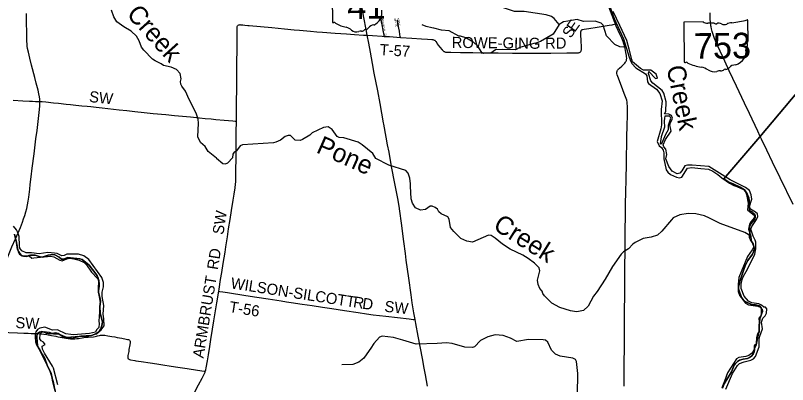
# Model space of a CAD drawing. Extents: x -51392 to 1635000, y 156707 to 696232.
# Drawn here: x 128704 to 149662, y 467379 to 477391 of the extents above; entities that cross this region are included whole.
import ezdxf

# ---------------------------------------------------------------- set-up
doc = ezdxf.new("R2010")
doc.units = 0
for name, color, linetype in [('GM_X_County_Road', 7, 'Continuous'), ('GM_X_Major_River', 7, 'Continuous'), ('GM_X_Major_River_Text', 7, 'Continuous'), ('GM_X_Minor_River', 7, 'Continuous'), ('GM_X_Minor_River_Text', 7, 'Continuous'), ('GM_X_State_Route', 7, 'Continuous'), ('GM_X_State_Shield', 7, 'Continuous'), ('GM_X_Township', 7, 'Continuous'), ('GM_X_Township_Road', 7, 'Continuous'), ('GM_X_Township_Road_Text', 7, 'Continuous'), ('GM_X_Township_Subdivision', 7, 'Continuous'), ('GM_X_Township_Subdivision_Text', 7, 'Continuous'), ('GM_X_US_Route', 7, 'Continuous')]:
    doc.layers.add(name, color=color, linetype=linetype)

msp = doc.modelspace()

# ---------------------------------------------------------------- linework, layer by layer
at = {"layer": 'GM_X_County_Road'}
for points in [[(144988, 477162), (144974, 477196), (144858, 477503), (144814, 477627), (144799, 477673), (144787, 477721), (144778, 477769), (144766, 477850), (144758, 477916)], [(145227, 467332), (145227, 467463), (145229, 467742), (145231, 468054), (145232, 468284), (145234, 468480), (145234, 468645), (145236, 468809), (145236, 468940), (145239, 469202), (145240, 469448), (145242, 469727), (145243, 470055), (145249, 470514), (145249, 470662), (145252, 470908), (145255, 471154), (145257, 471384), (145258, 471564), (145262, 471958), (145264, 472122), (145266, 472302), (145270, 472581), (145280, 472958), (145288, 473352), (145292, 473581), (145297, 473893), (145301, 474123), (145307, 474369), (145314, 474713), (145314, 474943), (145312, 474992), (145306, 475042), (145295, 475090), (145280, 475137), (145230, 475276), (145154, 475476), (145053, 475736), (145037, 475782), (145030, 475813), (145028, 475829), (145028, 475845), (145029, 475860), (145033, 475875), (145039, 475890), (145046, 475904), (145055, 475917), (145065, 475929), (145076, 475941), (145100, 475964), (145160, 476019), (145209, 476064), (145243, 476100), (145263, 476126), (145272, 476140), (145280, 476155), (145286, 476171), (145290, 476187), (145293, 476203), (145295, 476220), (145296, 476236), (145294, 476270), (145290, 476303), (145276, 476384), (145253, 476496), (145234, 476576), (145220, 476624), (145198, 476686), (145161, 476777), (145121, 476867), (145065, 476986), (145011, 477105), (144988, 477162)]]:
    msp.add_lwpolyline(points, dxfattribs=at)
at = {"layer": 'GM_X_Major_River'}
for points in [[(144803, 477732), (144953, 477307), (145102, 476988), (145207, 476761), (145359, 476262), (145411, 476143), (145437, 476087), (145546, 475971), (145810, 475810), (145841, 475757), (145863, 475591), (145883, 475541), (146106, 475394), (146198, 475271), (146257, 475073), (146234, 474841), (146238, 474424), (146224, 474314), (146127, 473973), (146174, 473857), (146236, 473805), (146288, 473733), (146305, 473662), (146299, 473503)], [(146357, 473505), (146381, 473616), (146354, 473760), (146300, 473825), (146288, 473883), (146347, 474027), (146506, 474251), (146470, 474427), (146481, 474489), (146519, 474549), (146535, 474603), (146508, 474677), (146440, 474712), (146318, 474722), (146354, 474784), (146369, 475049), (146304, 475281), (146256, 475351), (146003, 475553), (145953, 475619), (145886, 475819), (145898, 475871), (146073, 475685), (146131, 475686), (146092, 475801), (145948, 475911), (145752, 475906), (145670, 475950), (145457, 476137), (145431, 476199), (145364, 476474), (145299, 476709), (145109, 477118), (144924, 477495)], [(146322, 474605), (146311, 474526), (146318, 474358), (146231, 474097), (146200, 473913), (146252, 473917), (146359, 474173), (146432, 474299), (146426, 474413), (146495, 474607), (146463, 474658), (146329, 474656)], [(146329, 474656), (146322, 474605)], [(146299, 473503), (146369, 473200), (146414, 473144), (146482, 473081), (146647, 473001), (146727, 472989), (146791, 473004), (146944, 473250), (147062, 473269), (147310, 473238), (147520, 473219), (147636, 473167), (147773, 473080), (147881, 472983), (148086, 472841), (148205, 472782), (148285, 472751), (148463, 472667), (148520, 472603), (148550, 472536), (148592, 472295), (148574, 472119), (148767, 471965), (148754, 471897), (148663, 471794), (148631, 471732), (148601, 471596), (148662, 471407), (148677, 471292), (148732, 471160), (148735, 471103), (148703, 471034), (148573, 470850), (148338, 470287), (148320, 470091), (148333, 469974), (148421, 469709), (148522, 469588), (148599, 469545), (148853, 469509), (148915, 469478), (148973, 469426), (148982, 469357), (148935, 469242), (148906, 469164), (148873, 468761), (148814, 468459), (148732, 468275)], [(147988, 467253), (148166, 467680), (148301, 467896), (148361, 467951), (148484, 467999), (148668, 468037), (148741, 468075), (148789, 468144), (148888, 468398), (148892, 468610), (148906, 468687), (148980, 468886), (148958, 469067), (148989, 469181), (149051, 469247), (149092, 469316), (149103, 469429), (149067, 469481), (149015, 469475), (148950, 469534), (148878, 469567), (148692, 469598), (148606, 469637), (148481, 469779), (148407, 469980), (148404, 470106), (148431, 470232), (148460, 470302), (148586, 470525), (148770, 470919), (148801, 471057), (148805, 471237), (148779, 471298), (148728, 471406), (148669, 471593), (148688, 471665), (148822, 471858), (148853, 471938), (148845, 472007), (148794, 472057), (148654, 472139), (148633, 472207), (148689, 472405), (148674, 472529), (148625, 472640), (148523, 472727), (148105, 472933), (147525, 473293), (147075, 473333), (146944, 473330), (146874, 473308), (146793, 473175), (146734, 473115), (146664, 473094), (146528, 473165), (146437, 473296), (146357, 473505)], [(148732, 468275), (148684, 468217), (148615, 468170), (148529, 468138), (148335, 468116), (148276, 468074), (148028, 467698), (147952, 467472), (147879, 467288)]]:
    msp.add_lwpolyline(points, dxfattribs=at)
at = {"layer": 'GM_X_Minor_River'}
for points in [[(143460, 477143), (143330, 477310), (143256, 477360), (143113, 477411), (142509, 477497), (142254, 477494), (141899, 477619), (141475, 477674), (140841, 477787), (140457, 477962), (140338, 478077)], [(134164, 473520), (133933, 473701), (133855, 473836), (133726, 473948), (133654, 474095), (133676, 474467), (133668, 474575), (133607, 474740), (133422, 475109), (133319, 475338), (133221, 475472), (133192, 475527), (133188, 475597), (133206, 475675), (133177, 475817), (133077, 475928), (132935, 475988), (132721, 476037), (132661, 476083), (132498, 476164), (132428, 476204), (132185, 476447), (132127, 476532), (132062, 476700), (131990, 476825), (131843, 476961), (131645, 477086), (131457, 477215), (131376, 477351), (131313, 477538)], [(145272, 476551), (145218, 476535), (145112, 476541), (144970, 476606), (144751, 476839), (144654, 477132), (144604, 477186), (144441, 477236), (144122, 477223), (143947, 477278), (143702, 477239), (143576, 477221), (143460, 477143), (143297, 476885), (142960, 476682), (142827, 476638), (142773, 476629), (142391, 476526), (142280, 476458), (141926, 476469), (141732, 476460), (141608, 476372), (141419, 476356), (141360, 476385), (141252, 476555), (141137, 476670), (141085, 476698), (140929, 476787), (140787, 476833), (140737, 476829), (140475, 476974), (140265, 476989), (140061, 477042), (140005, 477052), (139851, 477087), (139742, 477135)], [(138486, 473513), (138403, 473647), (138118, 473880), (138002, 473957), (137620, 474072), (137492, 474083), (137440, 474107), (137297, 474300), (137189, 474368), (137063, 474352), (136756, 474203), (136698, 474147), (136497, 474024), (136431, 473998), (136299, 474012), (136172, 474133), (136104, 474139), (136023, 474105), (135899, 474005), (135775, 473950), (135709, 473940), (134870, 473884), (134800, 473851), (134701, 473721), (134639, 473687), (134603, 473631), (134592, 473531)], [(134164, 473520), (134329, 473378), (134401, 473368), (134467, 473391), (134592, 473531)], [(148662, 471407), (148500, 471502), (147836, 471751), (147547, 471891), (147409, 471953), (147173, 472013), (146967, 472019), (146740, 471980), (146561, 471900), (146511, 471846), (146246, 471538), (146129, 471430), (145960, 471380), (145739, 471345), (145526, 471233), (145464, 471185), (145340, 471064), (145213, 470983), (145147, 470919), (144912, 470581), (144714, 470238), (144497, 469901), (144398, 469779), (144251, 469504), (144124, 469391), (143988, 469358), (143929, 469350), (143767, 469376), (143478, 469472), (143259, 469586), (143068, 469786), (143019, 469851), (142999, 469911), (142942, 469982), (142893, 470095), (142873, 470207), (142938, 470467), (142916, 470543), (142797, 470671), (142618, 470801), (142473, 470890), (142134, 471049), (141927, 471185), (141724, 471353), (141614, 471424), (141548, 471429), (141108, 471242), (140954, 471268), (140796, 471339), (140606, 471533), (140511, 471640), (140479, 471863), (140441, 471926), (140256, 472007), (140194, 472062), (140161, 472132), (140095, 472185), (140019, 472220), (139965, 472222), (139832, 472131), (139698, 472112), (139564, 472173), (139483, 472296), (139444, 472413), (139429, 472764), (139424, 472826), (139409, 472977), (139366, 473115), (139297, 473182), (138843, 473334), (138486, 473513)], [(129850, 467367), (129734, 467821), (129709, 467875), (129489, 468226), (129434, 468338), (129425, 468416), (129506, 468464), (129464, 468526), (129398, 468567), (129367, 468623), (129374, 468746), (129420, 468803), (129485, 468817), (129617, 468800), (129740, 468751), (129875, 468753), (130088, 468667), (130329, 468681), (130383, 468687), (130625, 468683), (130908, 468759), (131033, 468866), (131110, 468974), (131100, 469160), (131089, 469284), (131107, 469525), (131061, 469768), (131054, 469888), (131093, 470030), (131090, 470144), (131046, 470285), (130695, 470775), (130556, 470867), (130418, 470914), (130348, 470912), (130098, 470914), (130027, 470877), (129961, 470868), (129834, 470931), (129766, 470947), (129586, 470959), (129351, 470923), (129143, 470951), (128995, 470952), (128877, 471007), (128826, 471080), (128810, 471150), (128802, 471397), (128787, 471447), (128755, 471521), (128736, 471572), (128653, 471672)], [(128690, 471432), (128754, 471132), (128775, 470980), (128814, 470917), (128882, 470873), (129080, 470867), (129152, 470810), (129206, 470812), (129663, 470862), (129745, 470845), (129908, 470750), (129974, 470737), (130099, 470792), (130181, 470806), (130235, 470797), (130291, 470785), (130431, 470751), (130566, 470688), (130630, 470625), (130768, 470430), (130935, 470258), (130965, 470200), (130947, 470041), (130952, 469913), (131004, 469608), (130969, 469099), (130975, 469035), (130963, 468923), (130900, 468867), (130876, 468797), (130710, 468764), (130277, 468724), (130207, 468733), (130067, 468750), (129845, 468862), (129709, 468855), (129498, 468933), (129369, 468912), (129301, 468869), (129254, 468811), (129242, 468739), (129237, 468661), (129248, 468534), (129271, 468456), (129370, 468303), (129425, 468168), (129541, 467962), (129626, 467765), (129727, 467458), (129781, 467185)], [(143958, 467107), (143967, 467678), (143932, 468005), (143904, 468055), (143832, 468094), (143492, 468149), (143361, 468200), (143255, 468315), (143159, 468527), (143089, 468579), (143032, 468596), (142627, 468597), (142316, 468546), (142137, 468636), (141941, 468709), (141727, 468723), (141522, 468673), (141329, 468576), (141163, 468403), (141109, 468382), (140905, 468392), (140555, 468491), (140407, 468506), (140153, 468494), (139584, 468477), (139216, 468584), (138970, 468656), (138658, 468693), (138590, 468664), (138428, 468491), (138349, 468367), (138306, 468303), (138164, 468096), (138025, 467985), (137860, 467924), (137566, 467913)]]:
    msp.add_lwpolyline(points, dxfattribs=at)
at = {"layer": 'GM_X_State_Route'}
for points in [[(138698, 474475), (138600, 475007), (138536, 475346), (138445, 475829), (138397, 476087), (138339, 476394), (138294, 476636), (138255, 476852), (138224, 477011), (138164, 477333), (138051, 477929), (138042, 477970), (138026, 478048), (138001, 478179), (137981, 478287)], [(147581, 477111), (147576, 477139), (147570, 477187), (147557, 477313), (147557, 477458)], [(149812, 472261), (149463, 472985), (149253, 473412), (149097, 473737), (148956, 474033), (148921, 474108), (148851, 474256), (148628, 474731), (148497, 475014), (148278, 475473), (148081, 475888), (147956, 476155), (147830, 476422), (147734, 476631), (147704, 476706), (147679, 476767), (147616, 476959), (147598, 477029), (147585, 477085), (147581, 477111)], [(139892, 467339), (139835, 467645), (139801, 467823), (139754, 468081), (139638, 468694), (139574, 469032), (139554, 469140), (139519, 469323), (139491, 469484), (139473, 469598), (139442, 469809), (139378, 470264), (139311, 470752), (139289, 470931), (139248, 471257), (139180, 471761), (139136, 472086), (139116, 472216), (139080, 472426), (139004, 472829), (138915, 473296), (138844, 473684), (138807, 473877), (138770, 474087), (138704, 474442), (138698, 474475)]]:
    msp.add_lwpolyline(points, dxfattribs=at)
at = {"layer": 'GM_X_State_Shield'}
for p, q in [((137297, 478273), (137307, 477217)), ((148589, 476700), (148584, 477253)), ((146844, 477192), (146854, 476136)), ((147371, 477216), (146861, 477211)), ((148589, 476701), (148589, 476700))]:
    msp.add_line(p, q, dxfattribs=at)
for centre, radius, start, end in [((138284, 477472), 369, 292.8474, 9.5244), ((137323, 477214), 16.3, 172.4969, 258.8452), ((137325, 477323), 124, 267.8775, 281.1424), ((137352, 477156), 44.8, 30.2869, 93.8103), ((137908, 478111), 1066, 240.9515, 257.737), ((137603, 476745), 334, 47.7227, 76.3745), ((138202, 476977), 31.8, 66.2903, 133.187), ((138187, 477122), 119, 283.4117, 323.8157), ((138445, 476931), 202, 94.9417, 143.1153), ((137960, 477157), 212, 231.2389, 286.8304), ((138086, 476792), 174, 86.2337, 111.7485), ((138099, 477079), 113, 269.3156, 316.0878)]:
    msp.add_arc(centre, radius, start, end, dxfattribs=at)
for centre, major_axis, start_param, end_param in [((147951, 478662), (1845, 17), 4.814394, 5.042369), ((148565, 477255), (19.4, 0.2), 6.141152, 7.989035), ((146864, 477195), (20.2, 0.2), 1.712693, 3.28349), ((147491, 477339), (196, 2), 4.042523, 4.731795), ((147563, 476624), (702, 7), 1.404758, 1.657858), ((147716, 477208), (56.4, 0.5), 3.836095, 5.185415), ((147800, 477087), (117, 1), 0.950623, 2.079405), ((147950, 477256), (141, 1), 4.081561, 5.145723), ((148203, 476901), (371, 3), 1.699011, 2.107814), ((148585, 476660), (30, 0.3), 1.883978, 3.671073), ((148395, 476588), (180, 2), 5.934695, 6.695948), ((148568, 476698), (20.7, 0.2), 5.05454, 6.418171), ((148075, 476394), (462, 4), 5.101752, 6.440018), ((148661, 476470), (131, 1), 2.387724, 3.262537), ((146874, 476134), (20.3, 0.2), 3.00124, 4.508301), ((146876, 476242), (155, 1), 4.665946, 4.897461), ((146910, 476075), (56, 0.5), 0.519207, 1.627899), ((147607, 477031), (1333, 13), 4.195997, 4.488961), ((147223, 475665), (417, 4), 0.823519, 1.323587), ((147953, 476044), (149, 1), 4.937069, 5.64225), ((148275, 475853), (253, 2), 1.647645, 2.488434), ((147670, 476077), (265, 2), 4.026481, 4.996735), ((147826, 475713), (217, 2), 1.495662, 1.94098), ((147843, 476000), (141, 1), 4.691044, 5.507374), ((147971, 475899), (39.7, 0.4), 1.147584, 2.315152)]:
    msp.add_ellipse(centre, major_axis=major_axis, ratio=0.8, start_param=start_param, end_param=end_param, dxfattribs=at)
at = {"layer": 'GM_X_Township'}
for points in [[(152114, 477913), (148909, 474096), (147936, 472955), (148047, 472875), (148207, 472813), (148377, 472734), (148489, 472659), (148569, 472551), (148611, 472445), (148628, 472288), (148622, 472180), (148628, 472128), (148648, 472078), (148704, 472062), (148756, 472013), (148782, 471963), (148787, 471911), (148765, 471853), (148671, 471747), (148634, 471683), (148630, 471633), (148638, 471527), (148626, 471423), (148629, 471363), (148653, 471307), (148727, 471196), (148755, 471090), (148755, 471038), (148741, 470980), (148706, 470920), (148583, 470746), (148515, 470600), (148464, 470470), (148367, 470176), (148329, 470017), (148327, 469955), (148334, 469895), (148368, 469791), (148456, 469683), (148508, 469634), (148680, 469546), (148796, 469539), (148900, 469511), (148946, 469461), (148958, 469406), (148952, 469290), (148932, 469238), (148895, 469182), (148899, 469082), (148887, 468974), (148888, 468810), (148858, 468758), (148826, 468652), (148817, 468487), (148765, 468437), (148768, 468321), (148756, 468269), (148726, 468205), (148682, 468147), (148630, 468113), (148573, 468089), (148461, 468068), (148353, 468042), (148299, 468008), (148248, 467954), (148216, 467902), (148141, 467726), (148037, 467564), (147944, 467398), (147898, 467284)], [(147898, 467284), (147944, 467398), (148037, 467564), (148141, 467726), (148216, 467902), (148248, 467954), (148299, 468008), (148353, 468042), (148461, 468068), (148573, 468089), (148630, 468113), (148682, 468147), (148726, 468205), (148756, 468269), (148768, 468321), (148765, 468437), (148817, 468487), (148826, 468652), (148858, 468758), (148888, 468810), (148887, 468974), (148899, 469082), (148895, 469182), (148932, 469238), (148952, 469290), (148958, 469406), (148946, 469461), (148900, 469511), (148796, 469539), (148680, 469546), (148508, 469634), (148456, 469683), (148368, 469791), (148334, 469895), (148327, 469955), (148329, 470017), (148367, 470176), (148464, 470470), (148515, 470600), (148583, 470746), (148706, 470920), (148741, 470980), (148755, 471038), (148755, 471090), (148727, 471196), (148653, 471307), (148629, 471363), (148626, 471423), (148638, 471527), (148630, 471633), (148634, 471683), (148671, 471747), (148765, 471853), (148787, 471911), (148782, 471963), (148756, 472013), (148704, 472062), (148648, 472078), (148628, 472128), (148622, 472180), (148628, 472288), (148611, 472445), (148569, 472551), (148489, 472659), (148377, 472734), (148207, 472813), (148047, 472875), (147936, 472955), (148909, 474096), (152114, 477913)], [(128677, 471456), (128728, 471229), (128760, 471041), (128796, 470983), (128822, 470930), (128868, 470880), (128924, 470858), (129014, 470852), (129064, 470876), (129116, 470887), (129240, 470889), (129379, 470847), (129431, 470838), (129593, 470886), (129715, 470904), (129777, 470901), (129887, 470837), (129955, 470779), (130014, 470780), (130118, 470822), (130448, 470793), (130512, 470769), (130704, 470618), (130890, 470385), (130926, 470325), (130950, 470263), (130975, 470128), (130975, 470048), (130955, 469924), (130955, 469874), (131000, 469704), (131008, 469639), (130995, 469485), (131001, 469315), (131064, 469076), (131062, 469016), (131020, 468892), (130987, 468840), (130941, 468788), (130887, 468754), (130767, 468707), (130482, 468694), (130310, 468652), (130255, 468628), (130197, 468644), (130075, 468647), (130023, 468655), (129863, 468762), (129801, 468786), (129647, 468758), (129538, 468773), (129486, 468797), (129416, 468815), (129358, 468803), (129306, 468767), (129293, 468727), (129288, 468711), (129282, 468655), (129305, 468441), (129331, 468379), (129367, 468324), (129426, 468202), (129500, 468084), (129562, 467907), (129677, 467674), (129705, 467554), (129715, 467448), (129782, 467211)], [(129782, 467211), (129715, 467448), (129705, 467554), (129677, 467674), (129562, 467907), (129500, 468084), (129426, 468202), (129367, 468324), (129331, 468379), (129305, 468441), (129282, 468655), (129288, 468711), (129293, 468727), (129306, 468767), (129358, 468803), (129416, 468815), (129486, 468797), (129538, 468773), (129647, 468758), (129801, 468786), (129863, 468762), (130023, 468655), (130075, 468647), (130197, 468644), (130255, 468628), (130310, 468652), (130482, 468694), (130767, 468707), (130887, 468754), (130941, 468788), (130987, 468840), (131020, 468892), (131062, 469016), (131064, 469076), (131001, 469315), (130995, 469485), (131008, 469639), (131000, 469704), (130955, 469874), (130955, 469924), (130975, 470048), (130975, 470128), (130950, 470263), (130926, 470325), (130890, 470385), (130704, 470618), (130512, 470769), (130448, 470793), (130118, 470822), (130014, 470780), (129955, 470779), (129887, 470837), (129777, 470901), (129715, 470904), (129593, 470886), (129431, 470838), (129379, 470847), (129240, 470889), (129116, 470887), (129064, 470876), (129014, 470852), (128924, 470858), (128868, 470880), (128822, 470930), (128796, 470983), (128760, 471041), (128728, 471229), (128677, 471456)]]:
    msp.add_lwpolyline(points, dxfattribs=at)
at = {"layer": 'GM_X_Township_Road'}
for points in [[(134702, 474522), (134702, 474568), (134703, 474618), (134704, 474831), (134705, 474929), (134708, 475126), (134709, 475323), (134711, 475651), (134714, 475930), (134716, 476176), (134718, 476405), (134721, 476898), (134721, 476947), (134719, 477062), (134719, 477078), (134722, 477094), (134728, 477109), (134738, 477122), (134751, 477132), (134766, 477137), (134781, 477141), (134796, 477142), (134815, 477141), (134845, 477139), (134877, 477136), (134927, 477130), (135010, 477122), (135044, 477119), (135664, 477062), (136007, 477029), (136269, 477005), (136416, 476992), (136710, 476964), (136889, 476948), (137036, 476937), (137380, 476912), (137691, 476889), (137903, 476874), (138149, 476857), (138255, 476852)], [(139154, 476795), (139169, 476794), (139464, 476774), (139726, 476757), (139889, 476746), (140004, 476739), (140037, 476735), (140054, 476731), (140070, 476725), (140085, 476718), (140098, 476708), (140110, 476695), (140120, 476682), (140154, 476625), (140182, 476585), (140223, 476534), (140287, 476459), (140309, 476436), (140322, 476425), (140335, 476416), (140348, 476409), (140363, 476402), (140378, 476398), (140394, 476395), (140410, 476393), (140442, 476392), (140524, 476392), (140787, 476389), (141115, 476385), (141345, 476380), (141804, 476375), (142198, 476370), (142526, 476368), (142805, 476369), (143002, 476368), (143232, 476369), (143675, 476375), (143839, 476375), (143954, 476376), (143970, 476377), (143986, 476379), (144002, 476382), (144016, 476387), (144030, 476395), (144041, 476405), (144051, 476416), (144058, 476430), (144063, 476444), (144066, 476460), (144067, 476476), (144067, 476525), (144059, 476722), (144052, 476853), (144049, 476903), (144048, 476936), (144051, 476953), (144056, 476969), (144064, 476984), (144076, 476997), (144090, 477006), (144105, 477013), (144138, 477021), (144269, 477040), (144495, 477077), (144657, 477103), (144820, 477128), (144900, 477141), (144988, 477162)], [(138255, 476852), (138399, 476843), (138661, 476827), (138712, 476824)], [(138712, 476824), (138858, 476816), (139154, 476795)], [(128644, 475090), (128906, 475076), (129086, 475066), (129168, 475062), (129250, 475058), (129332, 475057), (129368, 475057)], [(129368, 475057), (129380, 475057), (129429, 475055), (129527, 475046), (129739, 475024), (129870, 475010), (130082, 474988), (130196, 474975), (130343, 474961), (130506, 474943), (130653, 474928), (130750, 474917), (130897, 474903), (131060, 474884), (131207, 474867), (131517, 474834), (131729, 474810), (131941, 474787), (132202, 474761), (132446, 474735), (132789, 474700), (133018, 474679), (133458, 474637), (133703, 474614), (133850, 474600), (134014, 474585), (134144, 474572), (134373, 474551), (134601, 474529), (134667, 474524), (134702, 474522)], [(134222, 469909), (134231, 469964), (134272, 470224), (134304, 470418), (134342, 470661), (134392, 470968), (134414, 471114), (134458, 471389), (134491, 471600), (134531, 471859), (134570, 472102), (134614, 472377), (134639, 472539), (134666, 472717), (134678, 472815), (134683, 472880), (134685, 472946), (134686, 473060), (134687, 473241), (134691, 473470), (134694, 473765), (134697, 474077), (134697, 474224), (134699, 474337), (134700, 474416), (134702, 474522)], [(133858, 467732), (133864, 467749), (133874, 467781), (133884, 467829), (133915, 468023), (133941, 468185), (133978, 468411), (134011, 468605), (134056, 468880), (134092, 469107), (134172, 469592), (134222, 469909)], [(134222, 469909), (134246, 469905), (134329, 469893), (134459, 469874), (134961, 469795), (135252, 469751), (135560, 469703), (135917, 469650), (136063, 469627), (136192, 469607), (136484, 469563), (136759, 469521), (137035, 469478), (137294, 469438), (137634, 469387), (138007, 469333), (138234, 469299), (138413, 469274), (138754, 469232), (139390, 469158), (139498, 469146), (139554, 469140)], [(128127, 468825), (128166, 468818), (128264, 468810), (128378, 468802), (128526, 468795), (128755, 468786), (128935, 468777), (129050, 468772), (129132, 468767), (129246, 468763), (129307, 468761)], [(129307, 468761), (129361, 468759), (129410, 468755), (129475, 468747), (129556, 468733), (129588, 468728), (129637, 468720), (129685, 468711), (129798, 468688), (129830, 468683), (129862, 468676), (130023, 468643), (130071, 468635), (130137, 468627), (130202, 468622), (130268, 468620), (130317, 468621), (130366, 468625), (130414, 468630), (130512, 468646), (130609, 468661), (130674, 468668), (130821, 468677), (130870, 468683), (130902, 468690), (130934, 468699), (130981, 468712), (131014, 468717), (131046, 468720), (131079, 468719), (131128, 468714), (131209, 468702), (131322, 468683), (131403, 468669), (131467, 468656), (131596, 468633), (131709, 468611), (131741, 468605), (131773, 468597), (131788, 468590), (131801, 468581), (131811, 468569), (131817, 468554), (131819, 468537), (131819, 468521), (131808, 468456), (131785, 468327), (131777, 468278), (131756, 468165), (131751, 468132), (131750, 468116), (131752, 468100), (131758, 468085), (131768, 468072), (131781, 468063), (131796, 468057), (131828, 468049), (131942, 468032), (131974, 468026), (132120, 468004), (132363, 467966), (132542, 467939), (132704, 467914), (132931, 467879), (133109, 467851), (133368, 467811), (133644, 467767), (133822, 467738), (133858, 467732)], [(133249, 466473), (133271, 466527), (133314, 466633), (133345, 466708), (133371, 466768), (133398, 466828), (133434, 466902), (133540, 467105), (133677, 467367), (133774, 467556), (133833, 467674), (133853, 467718), (133858, 467732)]]:
    msp.add_lwpolyline(points, dxfattribs=at)
at = {"layer": 'GM_X_Township_Subdivision'}
for points in [[(138712, 476824), (138708, 476852), (138702, 476900), (138689, 476980), (138667, 477092), (138634, 477267), (138628, 477299)], [(139154, 476795), (139149, 476823), (139142, 476871), (139124, 476966), (139096, 477125), (139071, 477251), (139068, 477267)]]:
    msp.add_lwpolyline(points, dxfattribs=at)
at = {"layer": 'GM_X_US_Route'}
for points in [[(129091, 472677), (129107, 472805), (129132, 473017), (129160, 473245), (129210, 473636), (129261, 474043), (129292, 474271), (129332, 474593), (129359, 474841), (129367, 474939), (129370, 475005), (129368, 475054), (129368, 475057), (129363, 475120), (129354, 475185), (129338, 475266), (129316, 475362), (129267, 475553), (129226, 475712), (129140, 476045), (129092, 476236), (129055, 476396), (129035, 476492), (129025, 476556), (129019, 476621), (129016, 476687), (129012, 476818), (129010, 476982), (129007, 477146), (129005, 477244), (129000, 477441)], [(128199, 469358), (128207, 469418), (128283, 469987), (128315, 470198), (128332, 470295), (128356, 470407), (128379, 470503), (128401, 470581), (128426, 470659), (128466, 470767), (128514, 470889), (128610, 471115), (128705, 471335), (128740, 471416), (128837, 471643), (128892, 471780), (128926, 471872), (128957, 471966), (128984, 472061), (129009, 472156), (129029, 472253), (129047, 472350), (129063, 472464), (129091, 472677)]]:
    msp.add_lwpolyline(points, dxfattribs=at)

# ---------------------------------------------------------------- texts
at = {"layer": 'GM_X_Major_River_Text'}
msp.add_text('Creek', height=500, rotation=281.5374, dxfattribs=at).set_placement((146374, 475989))
at = {"layer": 'GM_X_Minor_River_Text'}
for s, rotation, p in [('Creek', 311.9608, (131698, 477410)), ('Pone', 335.9634, (136842, 473685)), ('Creek', 327.9615, (141639, 471609))]:
    msp.add_text(s, height=500, rotation=rotation, dxfattribs=at).set_placement(p)
at = {"layer": 'GM_X_State_Shield'}
for s, p in [('41', (137714, 477295)), ('753', (147121, 476213))]:
    msp.add_text(s, height=696.1, rotation=0.5385, dxfattribs=at).set_placement(p)
at = {"layer": 'GM_X_Township_Road_Text'}
for s, rotation, p in [('E', 54.4075, (143884, 476920)), ('S', 57.8079, (143779, 476753)), ('ROWE-GING', 359.3533, (140544, 476512)), ('T-57', 356.3082, (138584, 476320)), ('RD', 0.5386, (143080, 476488)), ('SW', 353.7468, (130692, 475046)), ('SW', 81.3733, (134347, 471431)), ('RD', 81.0016, (134197, 470478)), ('ARMBRUST', 80.7899, (133807, 468079)), ('WILSON-SILCOTT', 351.1833, (134533, 469990)), ('R', 350.5231, (137856, 469480)), ('D', 351.716, (138105, 469439)), ('T-56', 350.9009, (134489, 469347)), ('SW', 353.7008, (138708, 469357)), ('SW', 357.3347, (128698, 468912))]:
    msp.add_text(s, height=300, rotation=rotation, dxfattribs=at).set_placement(p)
at = {"layer": 'GM_X_Township_Subdivision_Text'}
for s, rotation, p in [('A', 280.0907, (138638, 477302)), ('D', 280.0907, (138645, 477259)), ('W', 285.3822, (138977, 477310)), ('A', 283.0745, (138992, 477255)), ('Y', 281.7328, (139002, 477213)), ('M', 286.1036, (139064, 477316)), ('A', 282.4058, (139079, 477266)), ('P', 280.5355, (139088, 477224)), ('A', 280.0692, (138653, 477215)), ('M', 280.0835, (138661, 477172)), ('S', 282.1474, (138670, 477118)), ('DR', 280.3232, (138684, 477056)), ('S', 280.7554, (139013, 477157)), ('E', 280.7554, (139020, 477122)), ('L', 280.4769, (139094, 477189)), ('E', 281.4286, (139101, 477153)), ('SE', 277.6585, (138716, 476902))]:
    msp.add_text(s, height=50, rotation=rotation, dxfattribs=at).set_placement(p)

doc.saveas('drawing.dxf')
